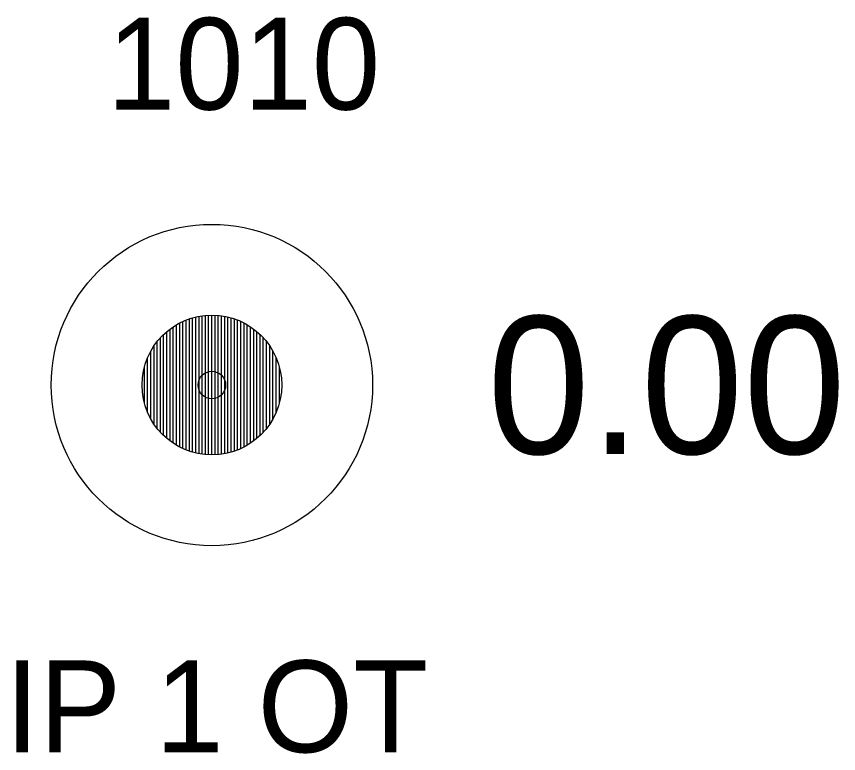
# Model space of a CAD drawing. Extents: x 1664393 to 1667175, y 987029 to 988607.
# Drawn here: x 1664959.55 to 1664968.5, y 987804.57 to 987812.6 of the extents above; entities that cross this region are included whole.
import ezdxf

# ---------------------------------------------------------------- set-up
doc = ezdxf.new("R2010")
doc.units = 0
for name, color, linetype in [('RD_EX_DV_Prop_txCode', 7, 'Continuous'), ('RD_EX_DV_PropPin', 7, 'Continuous'), ('RD_EX_TX_DV_Prop_ELEV', 7, 'Continuous'), ('RD_SMD_Locator', 7, 'Continuous')]:
    doc.layers.add(name, color=color, linetype=linetype)

msp = doc.modelspace()

# ---------------------------------------------------------------- linework, layer by layer
at = {"layer": 'RD_EX_DV_PropPin'}
for p, q in [((1664961.3992, 987807.8778), (1664961.3992, 987809.293)), ((1664961.4342, 987807.8649), (1664961.4342, 987809.3059)), ((1664961.4692, 987807.854), (1664961.4692, 987809.3168)), ((1664961.5042, 987807.8448), (1664961.5042, 987809.326)), ((1664961.5392, 987807.8374), (1664961.5392, 987809.3334)), ((1664961.5742, 987807.8317), (1664961.5742, 987809.3391)), ((1664961.6093, 987807.8276), (1664961.6093, 987809.3432)), ((1664961.6443, 987807.8252), (1664961.6443, 987809.3456)), ((1664961.6793, 987807.8244), (1664961.6793, 987809.3464)), ((1664961.7143, 987807.8252), (1664961.7143, 987809.3456)), ((1664961.7493, 987807.8276), (1664961.7493, 987809.3432)), ((1664961.7843, 987807.8317), (1664961.7843, 987809.3391)), ((1664961.8193, 987807.8374), (1664961.8193, 987809.3334)), ((1664961.8543, 987807.8448), (1664961.8543, 987809.326)), ((1664961.8894, 987807.854), (1664961.8894, 987809.3168)), ((1664961.9244, 987807.8649), (1664961.9244, 987809.3059)), ((1664961.9594, 987807.8778), (1664961.9594, 987809.293)), ((1664961.2591, 987807.9509), (1664961.2591, 987809.2199)), ((1664961.2941, 987807.929), (1664961.2941, 987809.2418)), ((1664961.3291, 987807.9097), (1664961.3291, 987809.2611)), ((1664961.3642, 987807.8927), (1664961.3642, 987809.2781)), ((1664961.9944, 987807.8927), (1664961.9944, 987809.2781)), ((1664962.0294, 987807.9097), (1664962.0294, 987809.2611)), ((1664962.0644, 987807.929), (1664962.0644, 987809.2418)), ((1664962.0994, 987807.9509), (1664962.0994, 987809.2199)), ((1664961.1541, 987808.0347), (1664961.1541, 987809.1361)), ((1664961.1891, 987808.0033), (1664961.1891, 987809.1675)), ((1664961.2241, 987807.9755), (1664961.2241, 987809.1953)), ((1664962.1345, 987807.9755), (1664962.1345, 987809.1953)), ((1664962.1695, 987808.0033), (1664962.1695, 987809.1675)), ((1664962.2045, 987808.0347), (1664962.2045, 987809.1361)), ((1664961.084, 987808.1112), (1664961.084, 987809.0596)), ((1664961.1191, 987808.0703), (1664961.1191, 987809.1005)), ((1664962.2395, 987808.0703), (1664962.2395, 987809.1005)), ((1664962.2745, 987808.1112), (1664962.2745, 987809.0596)), ((1664961.014, 987808.2159), (1664961.014, 987808.9549)), ((1664961.049, 987808.1589), (1664961.049, 987809.0119)), ((1664962.3095, 987808.1589), (1664962.3095, 987809.0119)), ((1664962.3445, 987808.2159), (1664962.3445, 987808.9549)), ((1664960.979, 987808.2875), (1664960.979, 987808.8833)), ((1664962.3796, 987808.2875), (1664962.3796, 987808.8833)), ((1664960.944, 987808.3892), (1664960.944, 987808.7816)), ((1664962.4146, 987808.3892), (1664962.4146, 987808.7816))]:
    msp.add_line(p, q, dxfattribs=at)
for radius in [1.75, 0.761]:
    msp.add_circle((1664961.6793, 987808.5854), radius, dxfattribs=at)
at = {"layer": 'RD_SMD_Locator'}
msp.add_circle((1664961.6793, 987808.5854), 0.15, dxfattribs=at)

# ---------------------------------------------------------------- texts
at = {"layer": 'RD_EX_DV_Prop_txCode'}
for s, p in [('1010', (1664960.5376, 987811.5854)), ('IP 1 OT', (1664959.4273, 987804.5854))]:
    msp.add_text(s, height=1, dxfattribs=at).set_placement(p)
at = {"layer": 'RD_EX_TX_DV_Prop_ELEV'}
msp.add_text('0.00', height=1.5, dxfattribs=at).set_placement((1664964.6793, 987807.8354))

doc.saveas('drawing.dxf')
